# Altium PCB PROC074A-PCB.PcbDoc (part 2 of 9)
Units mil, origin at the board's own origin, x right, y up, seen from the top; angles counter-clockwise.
Board outline 2755.91 x 5300 mil, 10 copper layers (Top Layer, L2-GND, L3-SIG1, L4-GND, L5-PWR/SIG, L6-SIG2, L7-PWR2, L8-SIG3, L9-GND, Bottom Layer), stack 67.57 mil thick; 585 components, 490 nets, 2137 pads, 1150 vias.
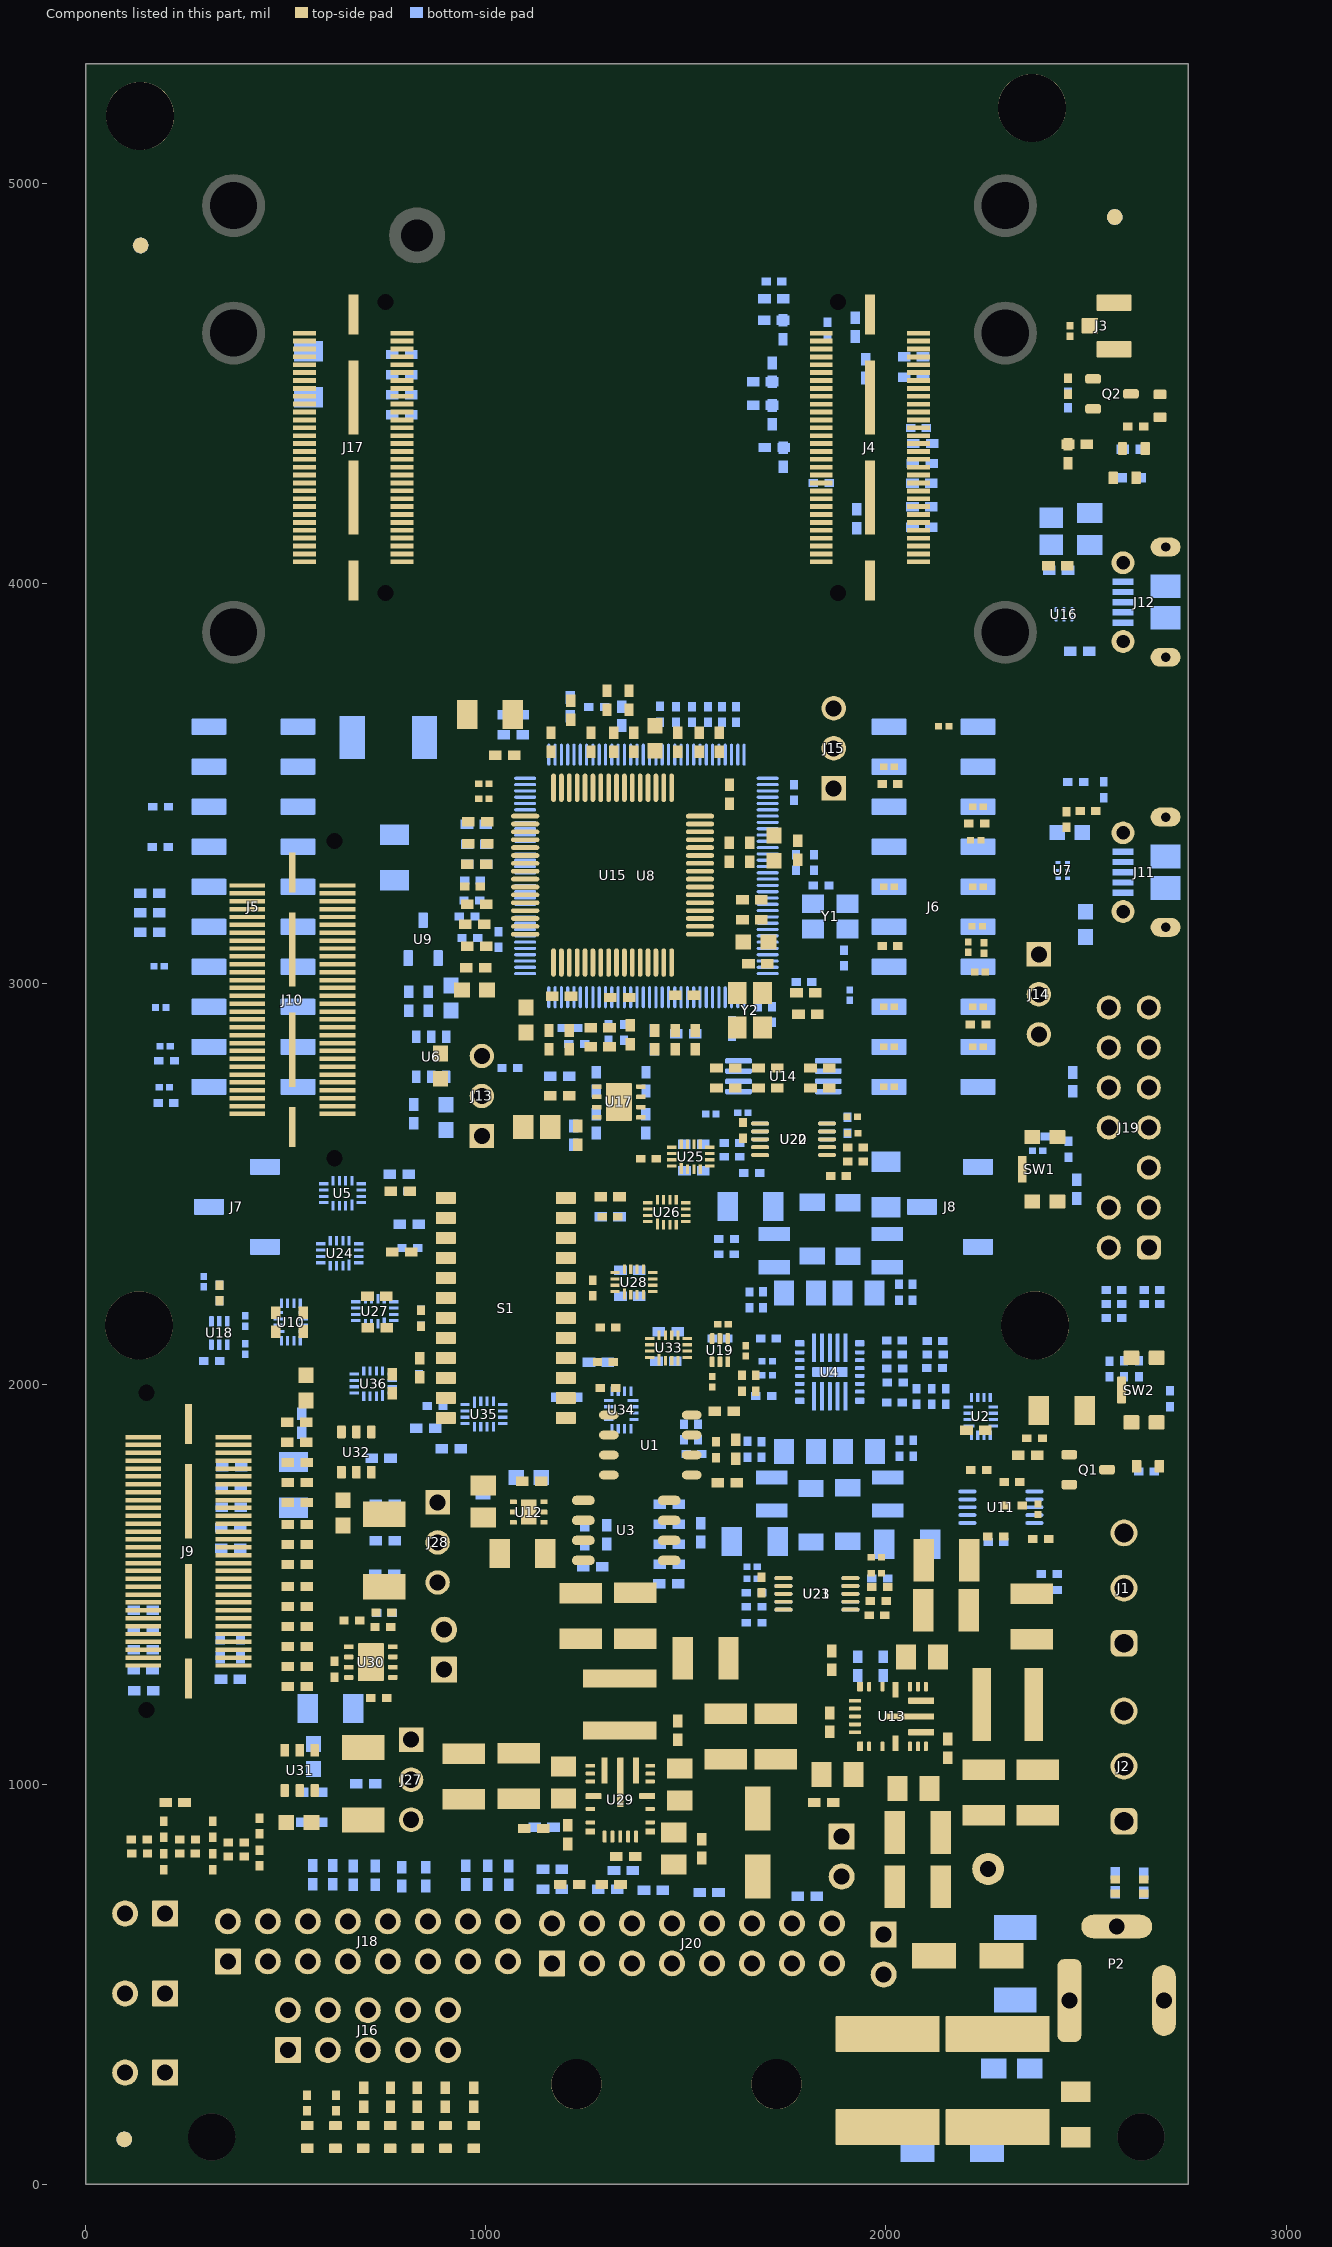
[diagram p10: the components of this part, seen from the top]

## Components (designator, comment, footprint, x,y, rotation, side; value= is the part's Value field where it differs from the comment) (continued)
R313 "CRCW0402280RFKED" 0402 2572.7,753.21 r90 bottom value=280
R314 "CRCW040210K0FKED" 0402L 1670.44,1443.27 r180 bottom value=10.0k
R315 "CRCW040210K0JNED" 0402 1119.37,889.06 r180 top value=10k
R316 "CRCW040210K0FKED" 0402L 1615.37,2568.06 r180 bottom value=10.0k
R317 "CRCW040210K0FKED" 0402L 1980.62,1457.53 r0 top value=10.0k
R318 "CRCW040210K0JNED" 0402 1204.37,874.06 r90 top value=10k
R319 "CRCW02010000Z0ED" 0201 1665.44,1543.27 r180 bottom value=0
R320 "CRCW02010000Z0ED" 0201 1642.37,2678.06 r180 bottom value=0
R321 "CRCW02010000Z0ED" 0201 1976.1,1566.69 r0 top value=0
R322 "CRCW02010000Z0ED" 0201 1665.44,1513.27 r180 bottom value=0
R323 "CRCW02010000Z0ED" 0201 1562.37,2675.06 r180 bottom value=0
R324 "CRCW02010000Z0ED" 0201 1976.1,1526.69 r0 top value=0
R325 "CRCW040210K0FKED" 0402L 1670.44,1478.27 r0 bottom value=10.0k
R326 "CRCW0402510RJNED" 0402 564.7,904.23 r180 bottom value=510
R327 "CRCW040210K0FKED" 0402L 1670.44,1403.27 r0 bottom value=10.0k
R328 "CRCW040210K0FKED" 0402L 1615.37,2602.06 r0 bottom value=10.0k
R329 "ERJ-2GEJ101X" 0402 690.62,1096.53 r180 bottom value=100
R330 "CRCW040210K0FKED" 0402L 1664.37,2527.06 r180 bottom value=10.0k
R331 "CRCW040210K0FKED" 0402L 1984.37,1493.06 r180 top value=10.0k
R332 "CRCW040210K0FKED" 0402L 1977.55,1422.07 r180 top value=10.0k
R338 "CRCW04024K70JNED" 0402 1310.37,2468.06 r0 top value=4.7k
R339 "CRCW04024K70JNED" 0402 727.75,2219.06 r0 top value=4.7k
R346 "ERJ-2GE0R00X" 0402 2090.01,4193.05 r0 bottom value=0
R347 "ERJ-2GE0R00X" 0402 1691.63,4505 r180 bottom value=0
R348 "ERJ-2GE0R00X" 0402 2090.01,4251.03 r0 bottom value=0
R349 "ERJ-2GE0R00X" 0402 1715.25,4528.62 r90 bottom value=0
R350 "ERJ-2GE0R00X" 0402 2455.01,4325.24 r270 top value=0
R351 "ERJ-2GE0R00X" 0402 2478.63,4348.87 r0 top value=0
R353 "ERJ-2GE0R00X" 0402 790,4573.35 r0 bottom value=0
R354 "ERJ-2GE0R00X" 0402 790,4523.35 r0 bottom value=0
R356 "ERJ-2GE0R00X" 0402 790,4473.35 r0 bottom value=0
R357 "ERJ-2GE0R00X" 0402 1719.01,4658.99 r180 bottom value=0
R358 "ERJ-2GE0R00X" 0402 1742.63,4635.37 r270 bottom value=0
R359 "ERJ-2GE0R00X" 0402 1691.63,4445.99 r180 bottom value=0
R360 "ERJ-2GE0R00X" 0402 1715.25,4422.37 r270 bottom value=0
R361 "ERJ-2GE0R00X" 0402 1743.25,4316.38 r270 bottom value=0
R362 "ERJ-2GE0R00X" 0402 1720.63,4341 r180 bottom value=0
R363 "CRCW0402510RJNED" 0402 539.37,1902.06 r270 bottom value=510
R364 "CRCW040210K0FKED" 0402 699.38,1001 r0 bottom value=10.0k
R367 "ERJ-2GEJ101X" 0402 694.38,911 r0 bottom value=100
R368 "ERJ-2GEJ101X" 0402 748.37,1699.06 r180 bottom value=100
R369 "CRCW040210K0FKED" 0402 748.75,1608.06 r0 bottom value=10.0k
R370 "ERJ-2GEJ101X" 0402 747.37,1525.06 r0 bottom value=100
R393 "CRCW02010000Z0ED" 0201_Silk 2245,3090 r270 top value=0
R394 "CRCW02010000Z0ED" 0201_Silk 2206,3092.01 r90 top value=0
R395 "CRCW040210K0FKED" 0402L 621.37,1287.06 r270 top value=10.0k
R396 "CRCW040214K0FKED" 0402L 745.05,1429.01 r0 top value=14.0k
R397 "PNM0402E3502BST1" 0402L 665.05,1409.01 r0 top value=35.0k
R398 "ERJ-2GE0R00X" 0402 790,4423.35 r0 bottom value=0
R399 "CRCW040210K0FKED" 0402L 2021.27,1953.8 r180 bottom value=10.0k
R400 "CRCW040210K0FKED" 0402L 1706.27,2113.8 r0 bottom value=10.0k
R401 "CRCW040210K0FKED" 0402L 2021.27,2108.8 r180 bottom value=10.0k
R402 "CRCW040210K0FKED" 0402L 1694.37,1970.06 r0 bottom value=10.0k
R403 "CRCW040210K0JNED" 0402 1993.37,1295.06 r90 bottom value=10k
R404 "CRCW040210K0JNED" 0402 1929.37,1295.06 r270 bottom value=10k
S1 "218-12LPST" SW_218-12LPST 1050,2190 r180 top
SW1 "KMR243GLFG" SW_KMR243GLFG 2397,2537 r90 top
SW2 "KMR243GLFG" SW_KMR243GLFG 2645,1985 r90 top
TP1 "5001" Keystone5001 2255.37,788.06 r90 top
U1 "TCAN1042HGVDQ1" D0008A_L 1410.94,1847.63 r180 top
U2 "TS3A5018RSVR" RSV0016A 2237.16,1919.11 r0 bottom
U3 "SN65HVDA540QDR" D0008A_N 1350.88,1634.28 r0 top
U4 "LP87524JRNFRQ1" RNF0026C 1859.65,2030.1 r0 bottom locked
U5 "TS3A5018RSVR" RSV0016A 641.63,2477 r90 bottom
U6 "TPS22917DBVR" DBV0006A_L 863.38,2818.06 r90 bottom
U7 "TPD4E004DRYR" DRY0006A#1 2442,3284 r0 bottom
U8 "TM4C1294NCPDTT3" PDT0128A 1401.34,3269.99 r0 bottom
U9 "LM4040C25QDBZR" DBZ0003A_N 843.02,3112 r90 bottom
U10 "TS3A5018RSVR" RSV0016A 512.37,2155.06 r0 bottom
U11 "INA226AIDGST" DGS0010A_L 2287.37,1692.06 r180 bottom
U12 "TPS61240DRVR" DRV0006A 1106.98,1680.06 r180 top
U13 "LM536353QRNLRQ1" RNL0022A 2014.09,1169.06 r90 top
U14 "93LC46B-I/ST" TSSOP-8 1743.65,2769.42 r0 bottom
U15 "FT4232HL" LQFP64_N 1316.69,3271.95 r180 top
U16 "TPD4E004DRYR" DRY0006A#2 2445,3924 r90 bottom
U17 "TPS79601DRBR" DRB0008B#1 1332.36,2705 r0 top
U18 "TMP112AIDRLR" DRL0006A 333.74,2127.66 r90 bottom
U19 "TMP112AIDRLR" DRL0006A 1585.08,2084.69 r270 top
U20 "INA226AIDGST" DGS0010A_L 1769.09,2611.69 r180 top
U21 "INA226AIDGST" DGS0010A_L 1827.4,1475.47 r0 bottom
U22 "INA226AIDGST" DGS0010A_L 1769.09,2611.69 r0 bottom
U23 "INA226AIDGST" DGS0010A_L 1827.4,1475.47 r180 top
U24 "TS3A5018RSVR" RSV0016A 634.63,2326.95 r90 bottom
U25 "TS3A5018RSVR" RSV0016A 1512.06,2568.38 r90 top
U26 "TS3A5018RSVR" RSV0016A 1452.24,2429.55 r90 top
U27 "TS3A5018RSVR" RSV0016A 722.37,2182.06 r90 bottom
U28 "TS3A5018RSVR" RSV0016A 1370,2255 r90 top
U29 "LM536255QRNLRQ1" RNL0022A 1335.93,960.36 r180 top
U30 "TPS79601DRBR" DRB0008B#2 712.41,1305 r180 top
U31 "TPS22917DBVR" DBV0006A_L 534.7,1034.23 r270 top
U32 "TPS22917DBVR" DBV0006A_L 676.37,1830.06 r90 top
U33 "TS3A5018RSVR" RSV0016A 1456.59,2090.24 r90 top
U34 "TS3A5018RSVR" RSV0016A 1338.75,1935.3 r180 bottom
U35 "TS3A5018RSVR" RSV0016A 995,1925 r270 bottom
U36 "TS3A5018RSVR" RSV0016A 718.37,2001.06 r90 bottom
Y1 "NX3225SA-16.000M-STD-CRS-2" NDK_NX3225SA 1861,3169 r270 bottom
Y2 "NX3225SA-12.000M-STD-CRS-2" NDK_NX3225SA 1659.85,2934.59 r180 top
ZZ1 "This Assembly Note is for PCB labels only" AssemblyNoteLabel -628,5874 r0 top
ZZ2 "These assemblies are ESD sensitive, ESD precautions shall be observed." AssemblyNote -628,5765.11 r0 top
ZZ3 "These assemblies must be clean and free from flux and all contaminants. Use of no clean flux is not acceptable." AssemblyNote -628,5676.56 r0 top
ZZ4 "These assemblies must comply with workmanship standards IPC-A-610 Class 2, unless otherwise specified." AssemblyNote -628,5588 r0 top

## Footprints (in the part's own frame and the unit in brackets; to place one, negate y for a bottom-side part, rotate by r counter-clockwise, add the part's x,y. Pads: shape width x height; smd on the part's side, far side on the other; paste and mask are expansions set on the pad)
0201 [mm] "Data from Kemet datasheet CC101_COM dated 7/28/11"
  rect 0.46x0.42 smd: 1(-0.33,0) 2(0.33,0)
  body extent -0.31,-0.16 0.31,0.16, height 0.26
0201_Silk [mm] "Data from Kemet datasheet CC101_COM dated 7/28/11"
  rect 0.46x0.42 smd: 1(-0.33,0) 2(0.33,0)
  silkscreen extent -0.75,-0.4 0.75,0.4, body extent -0.31,-0.16 0.31,0.16, height 0.26
0402 [mm] "0402 from SM-752 data"
  rect 0.8x0.6 smd: 1(-0.6,0) 2(0.6,0)
  silkscreen extent -1.22,-0.52 1.22,0.52, body extent -0.55,-0.3 0.55,0.3, height 0.6
0402_065 [mm] "0402"
  rect 0.8x0.6 smd: 1(-0.6,0) 2(0.6,0)
  silkscreen extent -1.22,-0.52 1.22,0.52, body extent -0.55,-0.3 0.55,0.3, height 0.65
0402_065L [mm] "0402"
  rect 0.6x0.5 smd: 1(-0.5,0) 2(0.5,0)
  body extent -0.55,-0.3 0.55,0.3, height 0.65
0402L [mm] "0402 from SM-752 data"
  rect 0.6x0.5 smd: 1(-0.5,0) 2(0.5,0)
  body extent -0.55,-0.3 0.55,0.3, height 0.6
597D_Z [mm] "SMD, 2-Leads, Body 6.2x6mm"
  rrect4% 2.3x6.6 smd: 1(-2.95,0) 2(2.95,0)
  body extent -4.5,-3.2 3.1,3.2, height 6.4
0603 [mm] "0603 from SM-752 data"
  rect 1x0.95 smd: 1(-0.8,0) 2(0.8,0)
  silkscreen extent -1.52,-0.69 1.52,0.69, body extent -0.87,-0.47 0.87,0.47, height 1
0805 [mm] "0805 from SM-752 data"
  rect 1.3x1.5 smd: 1(-0.85,0) 2(0.85,0)
  silkscreen extent -1.72,-0.97 1.72,0.97, body extent -1.1,-0.72 1.1,0.72, height 1.45
0805_HV [mil] "0805 with 30mil clearance between pads"
  rect 50x63 smd: 1(-40,0) 2(40,0)
  silkscreen extent -74,-40 74,40, body extent -43,-29 43,29, height 57
1206 [mm] "1206 from SM-752 data"
  rect 1.3x1.85 smd: 1(-1.45,0) 2(1.45,0)
  silkscreen extent -2.4,-1.21 2.4,1.21, body extent -1.7,-0.9 1.7,0.9, height 1.35
1206_180 [mm] "1206_180"
  rect 1.1x1.6 smd: 1(-1.7,0) 2(1.7,0)
  silkscreen extent -0.9,-1 0.9,1, body extent -1.75,-0.95 1.75,0.95, height 1.8
1210 [mm] "1210 from SM-752 data"
  rect 1.3x2.7 smd: 1(-1.45,0) 2(1.45,0)
  silkscreen extent -2.32,-1.57 2.32,1.57, body extent -1.7,-1.35 1.7,1.35, height 1.35
1210_270 [mm] "1210"
  rect 1.3x2.7 smd: 1(-1.45,0) 2(1.45,0)
  silkscreen extent -2.32,-1.57 2.32,1.57, body extent -1.7,-1.35 1.7,1.35, height 2.7
2010 [mm] "Chip Capacitor, Body 5.08x2.54mm, IPC Medium Density"
  rect 1.6x2.7 smd: 1(-2.3,0) 2(2.3,0)
  silkscreen extent -3.42,-1.65 3.42,1.65, body extent -2.73,-1.45 2.73,1.45, height 1.66
AssemblyNote [mil] "Assembly Note"
AssemblyNoteLabel [mil] "Assembly Note for PCB Labels"
CE_Mark_5mm [mil] "Minimum text height for CE Mark"
  silkscreen extent -138,-98 138,98
CONN_105017-0001 [mm] "Molex Micro USB-B"
  rect 0.4x1.35 smd: 1(-1.3,1.35) 2(-0.65,1.35) 3(0,1.35) 4(0.65,1.35) 5(1.3,1.35)
  oval 1.2x1.9 hole 0.6 slot 1.3 at 90 deg: 6(-3.5,-1.35) 9(3.5,-1.35)
  rect 1.5x1.9 smd: 7(-1,-1.35) 8(1,-1.35)
  round 1.45 hole 0.85: 10(2.5,1.35) 11(-2.5,1.35)
  Top Layer region: 3.5,-2.3 2.3,-2.3 2.3,-0.4 3.5,-0.4
  Top Layer region: -3.5,-0.4 -2.3,-0.4 -2.3,-2.3 -3.5,-2.3
  silkscreen extent -4.1,-0.2 4.1,1.4, body extent -4.1,-3.93 4.1,1.5, height 2.72
CUI_PJ-002AH [mm] "DC POWER JACK, R/A, TH"
  rrect50% 1.5x5.25 hole 1 square: 1(-3,0)
  oval 1.5x4.5 hole 1 square: 2(3,0)
  oval 4.5x1.5 hole 1 square: 3(0,4.7)
  silkscreen extent -4.1,-4.5 10.7,4.5, body extent -3.7,-4.5 10.7,4.9, height 11
D0008A_L [mm] "SOIC, 8-Leads, Body 4.9x3.9mm, Pitch 1.27mm, IPC High Density"
  oval 1.25x0.55 smd: 1(-2.625,1.905) 2(-2.625,0.635) 3(-2.625,-0.635) 4(-2.625,-1.905) 5(2.625,-1.905) 6(2.625,-0.635) 7(2.625,0.635) 8(2.625,1.905)
  silkscreen extent -3.1,-2.5 0.9,2.5, body extent -3,-2.45 3,2.45, height 1.63
D0008A_N [mm] "SOIC, 8-Leads, Body 4.9x3.9mm, Pitch 1.27mm, IPC Medium Density"
  oval 1.45x0.6 smd: 1(-2.725,1.905) 2(-2.725,0.635) 3(-2.725,-0.635) 4(-2.725,-1.905) 5(2.725,-1.905) 6(2.725,-0.635) 7(2.725,0.635) 8(2.725,1.905)
  silkscreen extent -3.3,-2.5 0.9,2.5, body extent -3,-2.45 3,2.45, height 1.63
DBV0006A_L [mm] "SOT23, 6-Leads, Body 2.9x1.6mm, Pitch 0.95mm, Lead Span 2.8mm, IPC High Density"
  rrect18% 0.8x0.55 smd: 1(-1.275,0.95) 2(-1.275,0) 3(-1.275,-0.95) 4(1.275,-0.95) 5(1.275,0) 6(1.275,0.95)
  silkscreen extent -1.55,-1.53 0.55,1.53, body extent -1.42,-1.46 1.42,1.46, height 1.12
DBZ0003A_N [mm] "SOT23, 3-Leads, Body 2.9x1.3mm, Pitch 0.95mm, Lead Span 2.4mm, IPC Medium Density"
  rrect17% 1x0.6 smd: 1(-1.2,0.95) 2(-1.2,-0.95) 3(1.2,0)
  silkscreen extent 0.2,-1.5 0.7,1.5, body extent -1.26,-1.46 1.26,1.46, height 0.98
DFE252012P [mm] "TOKO, Pad sizes increased as per request"
  rect 0.9x2 smd: 1(-1.05,0) 2(1.05,0)
  silkscreen extent -0.3,-1.2 0.3,1.2, body extent -1.35,-1.1 1.35,1.1, height 1.2
DGS0010A_L [mm] "TSSOP, 10-Leads, Body 3x3mm, Pitch 0.5mm, IPC High Density"
  oval 1.15x0.25 smd: 1(-2.125,1) 2(-2.125,0.5) 3(-2.125,0) 4(-2.125,-0.5) 5(-2.125,-1) 6(2.125,-1) 7(2.125,-0.5) 8(2.125,0) 9(2.125,0.5) 10(2.125,1)
  silkscreen extent -2.65,-1.55 0.9,1.55, body extent -2.45,-1.5 2.45,1.5, height 0.96
DRB0008B#1 [mm] "SON, 8-Leads, Body 3x3mm, Pitch 0.65mm, Thermal Pad 2.4x1.65mm, TI Recommended"
  rrect33% 0.6x0.3 smd: 1(-1.4,0.975) 2(-1.4,0.325) 3(-1.4,-0.325) 4(-1.4,-0.975) 5(1.4,-0.975) 6(1.4,-0.325) 7(1.4,0.325) 8(1.4,0.975)
  rrect9% 1.47x1.06 on Top Paste: 9(0,-0.63) 9(0,0.63)
  rrect6% 1.65x2.4 smd paste-1.2: 9(0,0)
  silkscreen extent -1.73,-1.73 1.73,1.73, body extent -1.5,-1.5 1.5,1.5, height 0.96
DRB0008B#2 [mm] "SON, 8-Leads, Body 3x3mm, Pitch 0.65mm, Thermal Pad 2.4x1.65mm, TI Recommended"
  rrect33% 0.6x0.3 smd: 1(-1.4,0.975) 2(-1.4,0.325) 3(-1.4,-0.325) 4(-1.4,-0.975) 5(1.4,-0.975) 6(1.4,-0.325) 7(1.4,0.325) 8(1.4,0.975)
  rrect6% 1.65x2.4 smd paste-1.2: 9(0,0)
  silkscreen extent -1.73,-1.73 1.73,1.73, body extent -1.5,-1.5 1.5,1.5, height 0.96
DRL0006A [mm] "SOTFL, 6-Flat Leads, Body 1.2x1.6x0.6mm, Pitch 0.5mm, TI recommended"
  rrect33% 0.67x0.3 smd: 1(-0.74,0.5) 2(-0.74,0) 3(-0.74,-0.5) 4(0.74,-0.5) 5(0.74,0) 6(0.74,0.5)
  silkscreen extent -0.9,-0.95 0.5,0.95, body extent -0.8,-0.8 0.8,0.8, height 0.61
DRV0006A [mm] "SON, 6-Leads, Body 2x2mm, Pitch 0.65mm, Thermal Pad 1.6x1mm, TI Recommended"
  rrect33% 0.45x0.3 smd: 1(-0.975,0.65) 2(-0.975,0) 3(-0.975,-0.65) 4(0.975,-0.65) 5(0.975,0) 6(0.975,0.65)
  rrect14% 1x0.7 on Top Paste: 7(0,0.45) 7(0,-0.45)
  rrect10% 1x1.6 smd paste-0.5: 7(0,0)
  silkscreen extent -1.05,-1.2 1.05,1.2, body extent -1.05,-1.05 1.05,1.05, height 0.81
DRY0006A#1 [mm] "PSON, 6-Leads, Body 1x1.45mm, Pitch 0.5mm, TI Recommended"
  rect 0.35x0.2 smd: 1(-0.275,0.5)
  rect 0.3x0.2 smd: 2(-0.3,0) 3(-0.3,-0.5) 4(0.3,-0.5) 5(0.3,0) 6(0.3,0.5)
  silkscreen extent -0.5,-0.85 0.2,0.85, body extent -0.53,-0.75 0.53,0.75, height 0.61
DRY0006A#2 [mm] "PSON, 6-Leads, Body 1x1.45mm, Pitch 0.5mm, TI Recommended"
  rrect50% 0.35x0.2 smd: 1(-0.275,0.5)
  rrect50% 0.3x0.2 smd: 2(-0.3,0) 3(-0.3,-0.5) 4(0.3,-0.5) 5(0.3,0) 6(0.3,0.5)
  body extent -0.5,-0.72 0.5,0.73, height 0.58
FCC_disclaimer [mil]
Fiducial10-20 [mm]
  round 1 smd mask+0.5: 1(0,0)
  Top Layer keep-out circle w1.178: c0,0 r0.5
IEC_HotSurface_Small [mil]
  silkscreen extent -107,-93 107,92
Johnson_128-0711-201 [mm] "UMC Straight Jack Receptacle, 50 Ohm, SMT"
  rrect10% 1x1.05 smd: 1(0,1.525)
  rrect10% 1.05x2.2 smd: 2(-1.475,0) 3(1.475,0)
  silkscreen extent -0.6,-1.3 0.6,-1.3, body extent -1.5,-1.55 1.5,1.55, height 1.25
Keystone5001 [mil] "For Keystone 500x miniature loop terminals"
  round 80 hole 40: 1(0,0)
  silkscreen extent -52,-52 52,52, body extent -49,-49 49,49, height 182
Label_650x200 [mil] "Thermal Transfer Label"
  round 1 on Mech13: 0(0,0)
  silkscreen extent -325,-100 325,100, body extent -325,-100 325,100, height 1
LQFP64_N [mm] "Thin QFP, 64-Leads, Body 10x10mm, Pitch 0.5mm, IPC Medium Density"
  oval 1.8x0.3 smd: 1(-5.55,3.75) 2(-5.55,3.25) 3(-5.55,2.75) 4(-5.55,2.25) 5(-5.55,1.75) 6(-5.55,1.25) 7(-5.55,0.75) 8(-5.55,0.25) 9(-5.55,-0.25) 10(-5.55,-0.75) 11(-5.55,-1.25) 12(-5.55,-1.75) 13(-5.55,-2.25) 14(-5.55,-2.75) 15(-5.55,-3.25) 16(-5.55,-3.75) 33(5.55,-3.75) 34(5.55,-3.25) 35(5.55,-2.75) 36(5.55,-2.25) 37(5.55,-1.75) 38(5.55,-1.25) 39(5.55,-0.75) 40(5.55,-0.25) 41(5.55,0.25) 42(5.55,0.75) 43(5.55,1.25) 44(5.55,1.75) 45(5.55,2.25) 46(5.55,2.75) 47(5.55,3.25) 48(5.55,3.75)
  oval 0.3x1.8 smd: 17(-3.75,-5.55) 18(-3.25,-5.55) 19(-2.75,-5.55) 20(-2.25,-5.55) 21(-1.75,-5.55) 22(-1.25,-5.55) 23(-0.75,-5.55) 24(-0.25,-5.55) 25(0.25,-5.55) 26(0.75,-5.55) 27(1.25,-5.55) 28(1.75,-5.55) 29(2.25,-5.55) 30(2.75,-5.55) 31(3.25,-5.55) 32(3.75,-5.55) 49(3.75,5.55) 50(3.25,5.55) 51(2.75,5.55) 52(2.25,5.55) 53(1.75,5.55) 54(1.25,5.55) 55(0.75,5.55) 56(0.25,5.55) 57(-0.25,5.55) 58(-0.75,5.55) 59(-1.25,5.55) 60(-1.75,5.55) 61(-2.25,5.55) 62(-2.75,5.55) 63(-3.25,5.55) 64(-3.75,5.55)
  silkscreen extent -5.68,-4.25 4.25,4.57, body extent -5,-5 5,5, height 1.6
Molex_0022284033 [mm] "Header, 2.54mm, 3x1, TH"
  rect 1.55x1.55 hole 1.02: 1(-2.54,0)
  round 1.55 hole 1.02: 2(0,0) 3(2.54,0)
  silkscreen extent -3.81,-1.24 3.81,1.5, body extent -3.81,-1.24 3.81,1.24, height 8.4
MTGNP431H431 [mil] "MOUNTING HOLE, NON PLATED, 4.318MM DRILL"
  round 170 hole 170 unplated: ""(0,0)
  Keep-Out Layer circle w0.98: c0,0 r125
  silkscreen extent -97,-97 97,97
NDK_NX3225SA [mm] "NDK"
  rect 1.2x1.4 smd: 1(-0.8,1.1) 2(-0.8,-1.1) 3(0.8,-1.1) 4(0.8,1.1)
  body extent -1.3,-1.65 1.3,1.65, height 0.7
On-Shore_OSTTE030161 [mm] "Terminal Block, 3.5mm, 3x1, TH"
  rrect50% 1.7x1.7 hole 1.2: 1(-3.5,0)
  round 1.7 hole 1.2: 2(0,0) 3(3.5,0)
  silkscreen extent -5.25,-3.6 5.25,4.05, body extent -5.75,-3.6 5.75,3.4, height 8.4
PDT0128A [mm] "Thin QFP, 128-Leads, Body 14x14mm, Pitch 0.4mm"
  oval 1.4x0.2 smd: 1(-7.7,6.2) 2(-7.7,5.8) 3(-7.7,5.4) 4(-7.7,5) 5(-7.7,4.6) 6(-7.7,4.2) 7(-7.7,3.8) 8(-7.7,3.4) 9(-7.7,3) 10(-7.7,2.6) 11(-7.7,2.2) 12(-7.7,1.8) 13(-7.7,1.4) 14(-7.7,1) 15(-7.7,0.6) 16(-7.7,0.2) 17(-7.7,-0.2) 18(-7.7,-0.6) 19(-7.7,-1) 20(-7.7,-1.4) 21(-7.7,-1.8) 22(-7.7,-2.2) 23(-7.7,-2.6) 24(-7.7,-3) 25(-7.7,-3.4) 26(-7.7,-3.8) 27(-7.7,-4.2) 28(-7.7,-4.6) 29(-7.7,-5) 30(-7.7,-5.4) 31(-7.7,-5.8) 32(-7.7,-6.2) 65(7.7,-6.2) 66(7.7,-5.8) 67(7.7,-5.4) 68(7.7,-5) 69(7.7,-4.6) 70(7.7,-4.2) 71(7.7,-3.8) 72(7.7,-3.4) 73(7.7,-3) 74(7.7,-2.6) 75(7.7,-2.2) 76(7.7,-1.8) 77(7.7,-1.4) 78(7.7,-1) 79(7.7,-0.6) 80(7.7,-0.2) 81(7.7,0.2) 82(7.7,0.6) 83(7.7,1) 84(7.7,1.4) 85(7.7,1.8) 86(7.7,2.2) 87(7.7,2.6) 88(7.7,3) 89(7.7,3.4) 90(7.7,3.8) 91(7.7,4.2) 92(7.7,4.6) 93(7.7,5) 94(7.7,5.4) 95(7.7,5.8) 96(7.7,6.2)
  oval 0.2x1.4 smd: 33(-6.2,-7.7) 34(-5.8,-7.7) 35(-5.4,-7.7) 36(-5,-7.7) 37(-4.6,-7.7) 38(-4.2,-7.7) 39(-3.8,-7.7) 40(-3.4,-7.7) 41(-3,-7.7) 42(-2.6,-7.7) 43(-2.2,-7.7) 44(-1.8,-7.7) 45(-1.4,-7.7) 46(-1,-7.7) 47(-0.6,-7.7) 48(-0.2,-7.7) 49(0.2,-7.7) 50(0.6,-7.7) 51(1,-7.7) 52(1.4,-7.7) 53(1.8,-7.7) 54(2.2,-7.7) 55(2.6,-7.7) 56(3,-7.7) 57(3.4,-7.7) 58(3.8,-7.7) 59(4.2,-7.7) 60(4.6,-7.7) 61(5,-7.7) 62(5.4,-7.7) 63(5.8,-7.7) 64(6.2,-7.7) 97(6.2,7.7) 98(5.8,7.7) 99(5.4,7.7) 100(5,7.7) 101(4.6,7.7) 102(4.2,7.7) 103(3.8,7.7) 104(3.4,7.7) 105(3,7.7) 106(2.6,7.7) 107(2.2,7.7) 108(1.8,7.7) 109(1.4,7.7) 110(1,7.7) 111(0.6,7.7) 112(0.2,7.7) 113(-0.2,7.7) 114(-0.6,7.7) 115(-1,7.7) 116(-1.4,7.7) 117(-1.8,7.7) 118(-2.2,7.7) 119(-2.6,7.7) 120(-3,7.7) 121(-3.4,7.7) 122(-3.8,7.7) 123(-4.2,7.7) 124(-4.6,7.7) 125(-5,7.7) 126(-5.4,7.7) 127(-5.8,7.7) 128(-6.2,7.7)
  silkscreen extent -7.2,-6.3 6.3,6.99, body extent -8,-8 8,8, height 1.07
RNF0026C [mm] "QFN, 26-Leads, Body 4x4.5mm, Pitch 0.5mm"
  rrect25% 0.6x0.4 smd paste-0.3: 1(-1.9,1.825) 8(-1.9,-1.825) 14(1.9,-1.825) 21(1.9,1.825)
  rrect40% 0.6x0.25 smd paste+0: 2(-1.9,1.25) 3(-1.9,0.75) 4(-1.9,0.25) 5(-1.9,-0.25) 6(-1.9,-0.75) 7(-1.9,-1.25) 15(1.9,-1.25) 16(1.9,-0.75) 17(1.9,-0.25) 18(1.9,0.25) 19(1.9,0.75) 20(1.9,1.25)
  rrect40% 0.25x1.82 smd paste-1: 9(-1,-1.54) 10(-0.5,-1.54) 11(0,-1.54) 12(0.5,-1.54) 13(1,-1.54) 22(1,1.54) 23(0.5,1.54) 24(0,1.54) 25(-0.5,1.54) 26(-1,1.54)
  rrect15% 2.24x0.66 smd paste-1: 27(0,0)
  rrect33% 0.6x0.3 on Bottom Paste: ""(-1.9,-1.775) ""(-1.9,1.775) ""(1.9,-1.775) ""(1.9,1.775)
  rrect33% 0.3x0.825 on Bottom Paste: ""(-1.575,-2.037) ""(-1.575,2.037) ""(1.575,-2.037) ""(1.575,2.037)
  rrect40% 0.25x0.81 on Bottom Paste: ""(-1,-2.045) ""(-1,-1.035) ""(-1,1.035) ""(-1,2.045) ""(-0.5,-2.045) ""(-0.5,-1.035) ""(-0.5,1.035) ""(-0.5,2.045) ""(0,-2.045) ""(0,-1.035) ""(0,1.035) ""(0,2.045) ""(0.5,-2.045) ""(0.5,-1.035) ""(0.5,1.035) ""(0.5,2.045) ""(1,-2.045) ""(1,-1.035) ""(1,1.035) ""(1,2.045)
  rrect15% 0.98x0.66 on Bottom Paste: ""(-0.59,0) ""(0.59,0)
  Top Layer region: -1.775,-2.4 -1.775,-1.675 -1.771,-1.656 -1.76,-1.64 -1.744,-1.629 -1.725,-1.625 -1.725,-1.625 -1.475,-1.625 -1.456,-1.629 -1.44,-1.64 -1.429,-1.656 -1.425,-1.675 -1.425,-1.675 -1.425,-2.4 -1.429,-2.419 -1.44,-2.435 -1.456,-2.446 -1.475,-2.45 -1.475,-2.45 -1.725,-2.45 -1.744,-2.446 -1.76,-2.435 -1.771,-2.419 -1.775,-2.4
  Top Layer region: 1.425,-2.4 1.425,-1.675 1.429,-1.656 1.44,-1.64 1.456,-1.629 1.475,-1.625 1.475,-1.625 1.725,-1.625 1.744,-1.629 1.76,-1.64 1.771,-1.656 1.775,-1.675 1.775,-1.675 1.775,-2.4 1.771,-2.419 1.76,-2.435 1.744,-2.446 1.725,-2.45 1.725,-2.45 1.475,-2.45 1.456,-2.446 1.44,-2.435 1.429,-2.419 1.425,-2.4
  Top Layer region: 1.425,1.675 1.425,2.4 1.429,2.419 1.44,2.435 1.456,2.446 1.475,2.45 1.475,2.45 1.725,2.45 1.744,2.446 1.76,2.435 1.771,2.419 1.775,2.4 1.775,2.4 1.775,1.675 1.771,1.656 1.76,1.64 1.744,1.629 1.725,1.625 1.725,1.625 1.475,1.625 1.456,1.629 1.44,1.64 1.429,1.656 1.425,1.675
  Top Layer region: -1.775,1.675 -1.775,2.4 -1.771,2.419 -1.76,2.435 -1.744,2.446 -1.725,2.45 -1.725,2.45 -1.475,2.45 -1.456,2.446 -1.44,2.435 -1.429,2.419 -1.425,2.4 -1.425,2.4 -1.425,1.675 -1.429,1.656 -1.44,1.64 -1.456,1.629 -1.475,1.625 -1.475,1.625 -1.725,1.625 -1.744,1.629 -1.76,1.64 -1.771,1.656 -1.775,1.675
  silkscreen extent -2.45,-2.7 2.45,2.7, body extent -2,-2.25 2,2.25, height 0.9
RNL0022A [mm] "VQFN-HR-22"
  rrect25% 0.6x0.4 smd: 1(-1.9,2) 17(1.9,2)
  rrect40% 0.6x0.25 smd: 2(-1.9,1.425) 3(-1.9,0.575) 5(-1.9,-1.175) 6(-1.9,-1.675) 7(-1.9,-2.175) 11(1.9,-2.175) 12(1.9,-1.675) 13(1.9,-1.175) 15(1.9,0.575) 16(1.9,1.425)
  rrect25% 1x0.4 smd paste-0.25: 4(-1.7,-0.25) 14(1.7,-0.25)
  rrect25% 0.4x0.4 on Top Paste: 4A(-2,-0.25) 4B(-1.4,-0.25) 14A(1.4,-0.25) 14B(2,-0.25)
  rrect25% 0.4x1.65 smd paste-0.25: 8(-1,-1.875) 10(1,-1.875)
  rrect25% 0.4x0.66 on Top Paste: 8A(-1,-1.445) 8B(-1,-2.305) 10A(1,-1.445) 10B(1,-2.305)
  rrect25% 0.4x3.15 smd paste-0.25: 9(0,-1.125)
  rrect25% 0.4x0.63 on Top Paste: 9A(0,0.12) 9B(0,-0.71) 9C(0,-1.54) 9D(0,-2.37)
  rrect40% 0.25x0.75 smd: 18(1,2.325) 19(0.5,2.325) 20(0,2.325) 21(-0.5,2.325) 22(-1,2.325)
  body extent -2,-2.5 2,2.5, height 0.9
RSV0016A [mm] "QFN, 16-Leads, Body 1.8x2.6mm, Pitch 0.4mm, TI Recommended"
  rect 0.7x0.2 smd: 1(-0.75,0.6)
  rect 0.6x0.2 smd: 2(-0.8,0.2) 3(-0.8,-0.2) 4(-0.8,-0.6) 9(0.8,-0.6) 10(0.8,-0.2) 11(0.8,0.2) 12(0.8,0.6)
  rect 0.2x0.6 smd: 5(-0.6,-1.2) 6(-0.2,-1.2) 7(0.2,-1.2) 8(0.6,-1.2) 13(0.6,1.2) 14(0.2,1.2) 15(-0.2,1.2) 16(-0.6,1.2)
  silkscreen extent -1.08,-1.33 1.08,1.45, body extent -0.92,-1.32 0.92,1.33, height 0.56
Samtec_QSH-030-01-X-D-A [mm] "Receptacle, 0.5 mm, 30x2, TH"
  rect 2.27x0.279 smd: 1(-2.865,7.25) 2(2.865,7.25) 3(-2.865,6.75) 4(2.865,6.75) 5(-2.865,6.25) 6(2.865,6.25) 7(-2.865,5.75) 8(2.865,5.75) 9(-2.865,5.25) 10(2.865,5.25) 11(-2.865,4.75) 12(2.865,4.75) 13(-2.865,4.25) 14(2.865,4.25) 15(-2.865,3.75) 16(2.865,3.75) 17(-2.865,3.25) 18(2.865,3.25) 19(-2.865,2.75) 20(2.865,2.75) 21(-2.865,2.25) 22(2.865,2.25) 23(-2.865,1.75) 24(2.865,1.75) 25(-2.865,1.25) 26(2.865,1.25) 27(-2.865,0.75) 28(2.865,0.75) 29(-2.865,0.25) 30(2.865,0.25) 31(-2.865,-0.25) 32(2.865,-0.25) 33(-2.865,-0.75) 34(2.865,-0.75) 35(-2.865,-1.25) 36(2.865,-1.25) 37(-2.865,-1.75) 38(2.865,-1.75) 39(-2.865,-2.25) 40(2.865,-2.25) 41(-2.865,-2.75) 42(2.865,-2.75) 43(-2.865,-3.25) 44(2.865,-3.25) 45(-2.865,-3.75) 46(2.865,-3.75) 47(-2.865,-4.25) 48(2.865,-4.25) 49(-2.865,-4.75) 50(2.865,-4.75) 51(-2.865,-5.25) 52(2.865,-5.25) 53(-2.865,-5.75) 54(2.865,-5.75) 55(-2.865,-6.25) 56(2.865,-6.25) 57(-2.865,-6.75) 58(2.865,-6.75) 59(-2.865,-7.25) 60(2.865,-7.25)
  round 0 hole 1.02 unplated mask+0.635: MH1(2.67,10.065) MH2(2.67,-10.065)
  rect 0.43x2.54 smd: MP1(0,8.065) MP4(0,-8.065)
  rect 0.43x4.7 smd: MP2(0,3.175) MP3(0,-3.175)
  silkscreen extent -3.9,-10.66 3.62,10.66, body extent -3.75,-10.64 3.75,10.67, height 3.25
Samtec_QTH-030-01-x-D-A [mil] "Header (Shrouded), 19.7mil, 30x2, SMT"
  rect 12x57 smd: 1(-285.7,121.5) 2(-285.7,-121.5) 3(-266,121.5) 4(-266,-121.5) 5(-246.3,121.5) 6(-246.3,-121.5) 7(-226.6,121.5) 8(-226.6,-121.5) 9(-206.9,121.5) 10(-206.9,-121.5) 11(-187.2,121.5) 12(-187.2,-121.5) 13(-167.5,121.5) 14(-167.5,-121.5) 15(-147.8,121.5) 16(-147.8,-121.5) 17(-128.1,121.5) 18(-128.1,-121.5) 19(-108.4,121.5) 20(-108.4,-121.5) 21(-88.7,121.5) 22(-88.7,-121.5) 23(-69,121.5) 24(-69,-121.5) 25(-49.3,121.5) 26(-49.3,-121.5) 27(-29.6,121.5) 28(-29.6,-121.5) 29(-9.9,121.5) 30(-9.9,-121.5) 31(9.8,121.5) 32(9.8,-121.5) 33(29.5,121.5) 34(29.5,-121.5) 35(49.2,121.5) 36(49.2,-121.5) 37(68.9,121.5) 38(68.9,-121.5) 39(88.6,121.5) 40(88.6,-121.5) 41(108.3,121.5) 42(108.3,-121.5) 43(128,121.5) 44(128,-121.5) 45(147.7,121.5) 46(147.7,-121.5) 47(167.4,121.5) 48(167.4,-121.5) 49(187.1,121.5) 50(187.1,-121.5) 51(206.8,121.5) 52(206.8,-121.5) 53(226.5,121.5) 54(226.5,-121.5) 55(246.2,121.5) 56(246.2,-121.5) 57(265.9,121.5) 58(265.9,-121.5) 59(285.6,121.5) 60(285.6,-121.5)
  round 28 hole 40 unplated mask+11.5: MH1(-364,80) MH2(364,80)
  rect 100x25 smd: MP1(-332.7,0) MP4(332.3,0)
  rect 185x25 smd: MP2(-125.2,0) MP3(124.8,0)
  silkscreen extent -394,-118 394,131, body extent -394,-140 394,140, height 170
Samtec_SSM-103-x-SV [mm] "Receptacle, 2.54mm, 3x1, SMT"
  rrect10% 1.02x1.905 smd: 1(-2.54,-1.777) 2(0,1.777) 3(2.54,-1.777)
  silkscreen extent -3.81,-2.28 3.81,1.28, body extent -3.81,-2.29 3.81,2.29, height 7.51
Samtec_SSM-110-x-DV [mm] "Receptacle, 2.54mm, 10x2, SMT"
  rrect10% 1.02x2.22 smd: 1(-11.43,2.825) 2(-11.43,-2.825) 3(-8.89,2.825) 4(-8.89,-2.825) 5(-6.35,2.825) 6(-6.35,-2.825) 7(-3.81,2.825) 8(-3.81,-2.825) 9(-1.27,2.825) 10(-1.27,-2.825) 11(1.27,2.825) 12(1.27,-2.825) 13(3.81,2.825) 14(3.81,-2.825) 15(6.35,2.825) 16(6.35,-2.825) 17(8.89,2.825) 18(8.89,-2.825) 19(11.43,2.825) 20(11.43,-2.825)
  silkscreen extent -13.02,-2.54 12.7,2.54, body extent -12.7,-3.52 12.7,3.52, height 7.42
Samtec_TSW-107-07-L-D-006 [mm] "Header, 2.54mm, 13 Pos, TH"
  rrect50% 1.53x1.53 hole 1.02: 1(-1.27,7.62)
  round 1.53 hole 1.02: 2(1.27,7.62) 3(-1.27,5.08) 4(1.27,5.08) 5(-1.27,2.54) 7(-1.27,0) 8(1.27,0) 9(-1.27,-2.54) 10(1.27,-2.54) 11(-1.27,-5.08) 12(1.27,-5.08) 13(-1.27,-7.62) 14(1.27,-7.62)
  body extent -2.54,-8.89 2.54,8.89, height 8.38
SM_RADIAL_C [mm] "5 x 5.8mm:  Panasonic C"
  rect 2.8x1.6 smd: 1(-2.15,0) 2(2.15,0)
  silkscreen extent -2.75,-2.75 2.75,2.75, body extent -2.75,-2.75 2.75,2.75, height 6.1
SMB [mil] "Molded Diode, 2-Leads, Body 5.4x3.6mm, IPC Medium Density, based on OnSemi component dimensions"
  rect 85x107.99 smd: 1(-87.01,0) 2(87.01,0)
  silkscreen extent -155,-82 125,82, body extent -106,-71 106,71, height 91
SML-P1_GREEN [mm] "ROHM"
  rect 0.5x0.6 smd: 1(-0.45,0) 2(0.45,0)
  silkscreen extent -0.95,-0.3 -0.95,0.3, body extent -0.53,-0.33 0.53,0.33, height 0.25
SOT-23 [mm] "SOT23, 3-Leads, Body 2.9x1.3mm, Pitch 0.95mm, Lead Span 2.5mm, IPC Medium Density"
  rrect50% 1x0.6 smd: 1(-1.2,0.95) 2(-1.2,-0.95) 3(1.2,0)
  silkscreen extent -1.63,-1.5 0.7,1.5, body extent -1.16,-1.45 1.21,1.45, height 1
STANDOFF_FAB_0022 [mm] "STANDOFF, 2 POS, THRU"
  round 3.18 hole 3.18 unplated: ""(-6.35,0) ""(6.35,0)
  Keep-Out Layer circle w0.05: c-6.35,0 r2.352
  Keep-Out Layer circle w0.05: c6.35,0 r2.352
  silkscreen extent -11.43,-6.35 11.43,6.35, body extent -11.43,-6.35 11.43,6.35, height 24.13
SW_218-12LPST [mm] "SMD, 24-Leads, Body 16.41x5.8mm, Pitch 1.27mm"
  rrect13% 1.27x0.76 smd: 1(-3.81,6.985) 2(-3.81,5.715) 3(-3.81,4.445) 4(-3.81,3.175) 5(-3.81,1.905) 6(-3.81,0.635) 7(-3.81,-0.635) 8(-3.81,-1.905) 9(-3.81,-3.175) 10(-3.81,-4.445) 11(-3.81,-5.715) 12(-3.81,-6.985) 13(3.81,-6.985) 14(3.81,-5.715) 15(3.81,-4.445) 16(3.81,-3.175) 17(3.81,-1.905) 18(3.81,-0.635) 19(3.81,0.635) 20(3.81,1.905) 21(3.81,3.175) 22(3.81,4.445) 23(3.81,5.715) 24(3.81,6.985)
  body extent -4.22,-8.2 4.22,8.2, height 2.63
SW_KMR243GLFG [mm] "SMD, 5-Leads, Body 4.2x2.8mm"
  rrect11% 0.9x1 smd: 1(-2.05,0.8) 2(2.05,0.8) 3(-2.05,-0.8) 4(2.05,-0.8)
  rrect18% 1.7x0.55 smd: 5(0,1.425)
  silkscreen extent -2.2,1.85 -1.79,2.26, body extent -2.3,-1.4 2.3,1.4, height 1.92
TI_Stacked_Overlay_Small [mil]
  silkscreen extent -418,-98 418,98
TLMx1000_Red [mm] "SMD, 2-Leads, Body 1.6x0.8mm"
  rrect17% 0.6x0.8 smd: 1(-0.725,0) 2(0.725,0)
  silkscreen extent -0.97,-0.8 1.6,0.8, body extent -0.85,-0.45 0.85,0.45, height 0.65
TLMx1000_Yellow [mm] "SMD, 2-Leads, Body 1.6x0.8mm"
  rrect17% 0.6x0.8 smd: 1(-0.725,0) 2(0.725,0)
  silkscreen extent -0.97,-0.8 1.6,0.8, body extent -0.85,-0.45 0.85,0.45, height 0.65
TSSOP-8 [mm] "TSSOP, 8-Leads, Body 3.1x4.5mm (max), Pitch 0.65mm, IPC Medium Density"
  rrect50% 1.7x0.35 smd: 1(-2.85,0.975) 2(-2.85,0.325) 3(-2.85,-0.325) 4(-2.85,-0.975) 5(2.85,-0.975) 6(2.85,-0.325) 7(2.85,0.325) 8(2.85,0.975)
  silkscreen extent -4.23,-1.55 1.6,1.55, body extent -3.2,-1.55 3.2,1.55, height 1.07
TSW-102-07-X-S [mm] "Samtec 100 mil 1x2 head, 230 mil above insulator"
  rrect6% 1.65x1.65 hole 1.016: 1(-1.27,0)
  round 1.65 hole 1.016: 2(1.27,0)
  silkscreen extent -3.42,-1.4 2.72,1.4, body extent -2.54,-1.27 2.54,1.27, height 8.38
TSW-105-07-G-D [mm] "Samtec 100mil, 2x5, 230 mil above insulator"
  rrect6% 1.65x1.65 hole 1.016: 1(-5.08,-1.27)
  round 1.65 hole 1.016: 2(-5.08,1.27) 3(-2.54,-1.27) 4(-2.54,1.27) 5(0,-1.27) 6(0,1.27) 7(2.54,-1.27) 8(2.54,1.27) 9(5.08,-1.27) 10(5.08,1.27)
  silkscreen extent -8,-2.54 6.35,2.54, body extent -6.35,-2.54 6.35,2.54, height 8.38
TSW-108-07-G-D [mm] "Samtec 100mil, 2x8, 230 mil above insulator"
  rrect6% 1.65x1.65 hole 1.016: 1(-8.89,-1.27)
  round 1.65 hole 1.016: 2(-8.89,1.27) 3(-6.35,-1.27) 4(-6.35,1.27) 5(-3.81,-1.27) 6(-3.81,1.27) 7(-1.27,-1.27) 8(-1.27,1.27) 9(1.27,-1.27) 10(1.27,1.27) 11(3.81,-1.27) 12(3.81,1.27) 13(6.35,-1.27) 14(6.35,1.27) 15(8.89,-1.27) 16(8.89,1.27)
  silkscreen extent -10.16,-4.24 10.16,2.54, body extent -10.16,-2.54 10.16,2.54, height 8.38
WEEE_Minimum [mil] "WEEElie bin"
  silkscreen extent -95,-172 99,104
XAL5030 [mil] "Coilcraft XAL5030 12/12/11"
  rect 46x183 smd: 1(-65,0) 2(65,0)
  silkscreen extent -108,-112 108,112, body extent -108,-112 108,112, height 122

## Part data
C1 C2 C4 C27 C32 C33 C34 C36 C40 C43 C44 C45 C49 C50 C52 C54 C55 C56 C57 C59 C63 C67 C68 C70 C72 C73 C92 C93 C94 C95 C114 C115 C116 C117: library part CMP-0078241-1, "CAP, CERM, 0.1 µF, 10 V,+/- 10%, X7R, 0402", Cap_Case=0402, Manufacturer=Kemet, Supplier Part Number 1=399-3520-1-ND, TempCo=X7R, Tolerance_%=10%, Value2=10V, ValueDisplayed=0.1µF
C3 C5: library part CMP-0078221-1, "CAP, CERM, 4700 pF, 50 V,+/- 10%, X7R, 0402", Cap_Case=0402, Manufacturer=TDK, Supplier Part Number 1=445-1258-1-ND, TempCo=X7R, Tolerance_%=10%, Value2=50V, ValueDisplayed=4700pF
C6 C7 C8 C25 C26 C71 C74 C77: library part CMP-0006325-2, "CAP, CERM, 0.1 uF, 50 V, +/- 10%, X7R, AEC-Q200 Grade 1, 0402", Cap_Case=0402, Manufacturer=TDK, Supplier Part Number 1=445-6899-1-ND, TempCo=X7R, Tolerance_%=10%, Value1="0.039064 ohm", Value2=50V, ValueDisplayed=0.1uF
C9 C10 C11 C12: library part CMP-0008017-2, "CAP, CERM, 10 uF, 10 V, +/- 10%, X7R, 0805", Cap_Case=0805, Manufacturer=MuRata, Supplier Part Number 1=490-10674-1-ND, TempCo=X7R, Tolerance_%=10%, Value1=Unknown, Value2=10V, ValueDisplayed=10uF
C13 C14 C15 C16: library part CMP-0008811-2, "CAP, CERM, 22 uF, 10 V, +/- 10%, X7R, AEC-Q200 Grade 1, 1206", Cap_Case=1206, Manufacturer=MuRata, TempCo=X7R, Tolerance_%=10%, Value1=Unknown, Value2=10V, ValueDisplayed=22uF
C17: library part CMP-0078265-1, "CAP, CERM, 0.22 µF, 16 V,+/- 10%, X7R, AEC-Q200 Grade 1, 0402", Cap_Case=0402, Manufacturer=MuRata, Supplier Part Number 1=490-10671-1-ND, TempCo=X7R, Tolerance_%=10%, Value2=16V, ValueDisplayed=0.22µF
C18 C19 C20 C21: library part CMP-0078223-1, "CAP, CERM, 390 pF, 50 V,+/- 5%, C0G/NP0, AEC-Q200 Grade 0, 0402", Cap_Case=0402, Manufacturer=TDK, Supplier Part Number 1=445-12137-1-ND, TempCo=C0G/NP0, Tolerance_%=5%, Value2=50V, ValueDisplayed=390pF
C22 C23: library part CMP-0082253-1, "CAP, TA, 47 µF, 50 V, +/- 10%, 0.24 ohm, SMD", Cap_Case=7.6x6x6.4mm, Manufacturer=Vishay-Sprague, Supplier Part Number 1=718-1408-1-ND, Tolerance_%=10%, Value1="0.24 ohm", Value2=50V, ValueDisplayed=47µF
C24: library part CMP-0006351-2, "CAP, CERM, 0.1 uF, 16 V, +/- 10%, X7R, 0402", Cap_Case=0402, Manufacturer=MuRata, Supplier Part Number 1=490-4759-2-ND, TempCo=X7R, Tolerance_%=10%, Value1=Unknown, Value2=16V, ValueDisplayed=0.1uF
C28: library part CMP-0007111-4, "CAP, CERM, 1 uF, 6.3 V, +/- 10%, X7R, 0603", Cap_Case=0603, Manufacturer="Samsung Electro-Mechanics", TempCo=X7R, Tolerance_%=10%, Value1=Unknown, Value2=6.3V, ValueDisplayed=1uF
C29: library part CMP-0007359-4, "CAP, CERM, 0.1 uF, 6.3 V, +/- 10%, X7R, 0603", Cap_Case=0603, Manufacturer=MuRata, Supplier Part Number 1=GRM188R70J104KA01D-ND, TempCo=X7R, Tolerance_%=10%, Value1=Unknown, Value2=6.3V, ValueDisplayed=0.1uF
C30 C110 C113: library part CMP-0006332-2, "CAP, CERM, 1000 pF, 100 V, +/- 10%, X7S, AEC-Q200 Grade 1, 0402", Cap_Case=0402, Manufacturer=TDK, Supplier Part Number 1=445-6904-1-ND, TempCo=X7S, Tolerance_%=10%, Value1="2.71151 ohm", Value2=100V, ValueDisplayed=1000pF
C31 C66 C69 C111: library part CMP-0007136-5, "CAP, CERM, 1 uF, 16 V, +/- 10%, X7R, AEC-Q200 Grade 1, 0603", Cap_Case=0603, Manufacturer=MuRata, Supplier Part Number 1=490-5241-6-ND, TempCo=X7R, Tolerance_%=10%, Value1=Unknown, Value2=16V, ValueDisplayed=1uF
C35 C37 C41 C120: library part CMP-0078222-1, "CAP, CERM, 1 µF, 6.3 V,+/- 20%, X7S, 0402", Cap_Case=0402, Manufacturer=TDK, Supplier Part Number 1=445-9080-1-ND, TempCo=X7S, Tolerance_%=20%, Value2=6.3V, ValueDisplayed=1µF
C38: library part CMP-0078220-1, "CAP, CERM, 0.01 µF, 25 V,+/- 10%, X7R, 0402", Cap_Case=0402, Manufacturer=TDK, Supplier Part Number 1=445-1260-1-ND, TempCo=X7R, Tolerance_%=10%, Value2=25V, ValueDisplayed=0.01µF
C39 C62 C65 C88: library part CMP-0006302-2, "CAP, CERM, 2.2 uF, 10 V, +/- 10%, X7S, 0402", Cap_Case=0402_065, Manufacturer=TDK, Supplier Part Number 1=445-9097-1-ND, TempCo=X7S, Tolerance_%=10%, Value1="0.005925 ohm", Value2=10V, ValueDisplayed=2.2uF
C42 C46: library part CMP-0078218-1, "CAP, CERM, 0.01 µF, 16 V,+/- 10%, X7R, 0402", Cap_Case=0402, Manufacturer=Kemet, Supplier Part Number 1=399-1038-1-ND, TempCo=X7R, Tolerance_%=10%, Value2=16V, ValueDisplayed=0.01µF
C47 C48 C60 C61: library part CMP-0006494-2, "CAP, CERM, 8 pF, 50 V, +/- 6%, C0G/NP0, 0402", Cap_Case=0402, Manufacturer=MuRata, Supplier Part Number 1=490-5867-1-ND, TempCo=C0G/NP0, Tolerance_%=6%, Value1=Unknown, Value2=50V, ValueDisplayed=8pF
C51 C53 C58: library part CMP-0007058-4, "CAP, CERM, 4.7 uF, 10 V, +/- 10%, X7S, 0603", Cap_Case=0603, Manufacturer=TDK, Supplier Part Number 1=445-14258-1-ND, TempCo=X7S, Tolerance_%=10%, Value1=Unknown, Value2=10V, ValueDisplayed=4.7uF
C64: library part CMP-0078217-1, "CAP, CERM, 15 pF, 50 V,+/- 1%, C0G/NP0, 0402", Cap_Case=0402, Manufacturer=AVX, Supplier Part Number 1=478-5126-1-ND, TempCo=C0G/NP0, Tolerance_%=1%, Value2=50V, ValueDisplayed=15pF
C75 C76: library part CMP-0006906-5, "CAP, CERM, 2.2 uF, 10 V, +/- 10%, X5R, 0603", Cap_Case=0603, Manufacturer=Kemet, Supplier Part Number 1=399-4911-1-ND, TempCo=X5R, Tolerance_%=10%, Value1=Unknown, Value2=10V, ValueDisplayed=2.2uF
C78 C96: library part CMP-0006717-2, "CAP, CERM, 0.47 uF, 6.3 V, +/- 10%, X7R, 0402", Cap_Case=0402, Manufacturer="Taiyo Yuden", Supplier Part Number 1=587-3765-1-ND, TempCo=X7R, Tolerance_%=10%, Value1=Unknown, Value2=6.3V, ValueDisplayed=0.47uF
C79 C97: library part CMP-0011176-2, "CAP, AL, 10 uF, 50 V, +/- 20%, 1.52 ohm, AEC-Q200 Grade 2, SMD", Cap_Case=C, Manufacturer=Panasonic, Supplier Part Number 1=PCE3808CT-ND, Tolerance_%=20%, Value1="1.52 ohm", Value2=50V, ValueDisplayed=10uF
C80 C83 C98 C101: library part CMP-0009227-2, "CAP, CERM, 10 uF, 50 V, +/- 20%, X7R, 1210", Cap_Case=1210, Manufacturer=MuRata, Supplier Part Number 1=490-12775-1-ND, TempCo=X7R, Tolerance_%=20%, Value1=Unknown, Value2=50V, ValueDisplayed=10uF
C81 C84 C99 C102: library part CMP-0009075-1, "CAP, CERM, 0.1 uF, 50 V, +/- 10%, X7R, 1210", Cap_Case=1210, Manufacturer=Kemet, Supplier Part Number 1=399-1267-1-ND, TempCo=X7R, Tolerance_%=10%, Value1=Unknown, Value2=50V, ValueDisplayed=0.1uF
C82 C85 C100 C103: library part CMP-0007718-2, "CAP, CERM, 0.01 uF, 50 V, +/- 10%, X7R, 0805", Cap_Case=0805, Manufacturer=Kemet, Supplier Part Number 1=399-1158-1-ND, TempCo=X7R, Tolerance_%=10%, Value1="1.739 ohm", Value2=50V, ValueDisplayed=0.01uF
C86 C104: library part CMP-0006201-2, "CAP, CERM, 0.1 uF, 16 V, +/- 10%, X7R, 0402", Cap_Case=0402, Manufacturer=AVX, Supplier Part Number 1=478-7888-1-ND, TempCo=X7R, Tolerance_%=10%, Value1=Unknown, Value2=16V, ValueDisplayed=0.1uF
C87 C108: library part CMP-0007870-2, "CAP, CERM, 4.7 uF, 25 V, +/- 10%, X7R, 0805", Cap_Case=0805, Manufacturer=TDK, Supplier Part Number 1=445-5972-1-ND, TempCo=X7R, Tolerance_%=10%, Value1=Unknown, Value2=25V, ValueDisplayed=4.7uF
C89 C90 C91 C105 C106 C107: library part CMP-0081783-1, "CAP, CERM, 22 µF, 16 V,+/- 10%, X7R, 1210", Cap_Case=1210, Manufacturer=Samsung, Supplier Part Number 1=1276-3394-1-ND, TempCo=X7R, Tolerance_%=10%, Value2=16V, ValueDisplayed=22µF
C109 C112: library part CMP-0006856-6, "CAP, CERM, 0.1 uF, 25 V, +/- 5%, X7R, 0603", Cap_Case=0603, Manufacturer=Kemet, Supplier Part Number 1=399-1282-1-ND, TempCo=X7R, Tolerance_%=5%, Value1=Unknown, Value2=25V, ValueDisplayed=0.1uF
C119: library part CMP-0006242-2, "CAP, CERM, 33 pF, 50 V, +/- 5%, C0G/NP0, 0402", Cap_Case=0402, Manufacturer=Kemet, Supplier Part Number 1=399-1017-1-ND, TempCo=C0G/NP0, Tolerance_%=5%, Value1=Unknown, Value2=50V, ValueDisplayed=33pF
"CAUTION HOT SURFACE1": library part CMP-0074837-1, "IEC 61010-1 Hot Surface Warning"
D1: library part CMP-0005561-2, "Diode, TVS, Uni, 30 V, 48.4 Vc, SMB", Manufacturer="Diodes Inc.", Power_W=5W, Supplier Part Number 1=SMBJ30A-FDICT-ND
D4 D5 D6 D7 DS1 DS2: library part CMP-0078196-1, "LED, Yellow, SMD", Color=yellow, Manufacturer=Vishay-Semiconductor, Power_TotalModule=40mW, Supplier Part Number 1=TLMY1000-GS08CT-ND, Value1=.04W, Value2=1.8V
D8 D9 D10 DS3 DS4: library part CMP-0078197-1, "LED, Red, SMD", Color=Red, Manufacturer=Vishay-Semiconductor, Power_TotalModule=40mW, Supplier Part Number 1=TLMS1000-GS08CT-ND, Value1=.04W, Value2=1.8V
D11 D14: library part CMP-0002873-1, "LED, Green, SMD", Color=green, Manufacturer=Rohm, Supplier Part Number 1=511-1592-1-ND, Value1=W, Value2=2.2V
F1: library part CMP-0003458-1, "Fuse, 5 A, 32VAC/VDC, SMD", Irating_A=5A, Manufacturer=Littelfuse, Supplier Part Number 1=F1608CT-ND
FB1 FB2: library part CMP-0003364-1, "Ferrite Bead, 30 ohm @ 100 MHz, 4 A, 0805", Manufacturer=MuRata, Supplier Part Number 1=490-11049-1-ND, Value1="0.014 ohm", Value2=4A, ValueDisplayed="30 ohm"
FID1 FID2 FID3 FID4 FID5 FID6: library part CMP-0077181-1, "Fiducial mark.  There is nothing to buy or mount.", Manufacturer=N/A
J1 J2: library part CMP-0075352-1, "Terminal Block, 3.5mm, 3x1, Tin, R/A, TH", Color=Blue, Current_A=10A, Manufacturer="On-Shore Technology", Supplier Part Number 1=ED2636-ND, Voltage_V=125V
J3: library part CMP-0055788-1, "UMC Straight Jack Receptacle, 50 Ohm, Gold, SMT", Manufacturer="Cinch Connectivity", Supplier Part Number 1=J983CT-ND
J4 J17: library part CMP-0075558-2, "Header(Shrouded), 19.7mil, 30x2, Gold, SMT", Manufacturer=Samtec, Supplier Part Number 1=SAM8185-ND
J5 J6: library part CMP-0078182-1, "Receptacle, 2.54mm, 10x2, Gold with Tin tail, SMT", Color=Black, Current_A=5.2A, Manufacturer=Samtec, Supplier Part Number 1=SAM1150-10-ND, Voltage_V=405V
J7 J8: library part CMP-0078183-1, "Receptacle, 2.54mm, 3x1, Gold with Tin tail, SMT", Color=Black, Current_A=5.2A, Manufacturer=Samtec, Supplier Part Number 1=SAM1152-03-ND, Voltage_V=405V
J9 J10: library part CMP-0075524-1, "Receptacle, 0.5 mm, 30x2, Gold, TH", Color=Black, Manufacturer=Samtec, Supplier Part Number 1=SAM8180-ND
J11 J12: library part CMP-0055293-1, "Connector, Receptacle, Micro-USB Type B, R/A, Bottom Mount SMT", Manufacturer=Molex, Supplier Part Number 1=WM1399CT-ND
J13 J14 J15 J27 J28: library part CMP-0055332-1, "Header, 2.54mm, 3x1, Tin, TH", Color=Black, Current_A=4A, Manufacturer=Molex, Supplier Part Number 1=WM50016-03-ND, Voltage_V=250V
J16: library part CMP-0075410-2, "Header, 100mil, 5x2, Gold, TH", Color=Black, Current_A=6.3A, Manufacturer=Samtec, Supplier Part Number 1=SAM1028-05-ND, Voltage_V=550V
J18 J20: library part CMP-0075418-1, "Header, 100mil, 8x2, Gold, TH", Color=Black, Current_A=6.3A, Manufacturer=Samtec, Supplier Part Number 1=SAM1028-08-ND, Voltage_V=550V
J19: library part CMP-0081507-3, "Header, 2.54mm, 13Pos, Gold with Tin tail, TH", Color=Black, Manufacturer=Samtec, Supplier Part Number 1=TSW-107-07-L-D-006-ND
L1 L2 L3 L4: library part CMP-0058946-1, "Inductor, Shielded, 470 nH, 4.7 A, 0.021 ohm, SMD", Manufacturer="MuRata Toko", PartNumber=DFE252012P-R47M{}P2, Value1="0.021 ohm", Value2=4.7A, ValueDisplayed=470nH
L5 L6: library part CMP-0081523-1, "Ferrite Bead, 600 ohm @ 100 MHz, 0.3 A, 0402", Manufacturer=MuRata, Supplier Part Number 1=490-3998-1-ND, Value1="0.7 ohm", Value2=0.3A, ValueDisplayed="600 ohm"
L7: library part CMP-0058739-1, "Inductor, Multilayer, Ferrite, 1 uH, 0.8 A, 0.19 ohm, SMD", Manufacturer=MuRata, Supplier Part Number 1=490-4992-1-ND, Value1="0.19 ohm", Value2=0.8A, ValueDisplayed=1uH
L8 L9: library part CMP-0061001-1, "Inductor, Shielded, Composite, 2.2 uH, 9.2 A, 0.01 ohm, SMD", Manufacturer=Coilcraft, Value1="0.01 ohm", Value2=9.2A, ValueDisplayed=2.2uH
LBL1: library part CMP-0003625-1, "Thermal Transfer Printable Labels, 0.650\" W x 0.200\" H - 10,000 per roll", Manufacturer=Brady, Supplier Part Number 1=97C5133
Logo1: library part CMP-0074838-1, "Texas Instrument Corporate Signature"
Logo2: library part CMP-0074844-1
Logo3: library part CMP-0074847-1, "FCC_disclaimer"
Logo4: library part CMP-0074769-1
P1 P3 P4 P5 P6 P7: library part CMP-0075405-1, "Header, 100mil, 2x1, Gold, TH", Color=Black, Current_A=6.3A, Manufacturer=Samtec, Supplier Part Number 1=SAM1029-02-ND, Voltage_V=550V
P2: library part CMP-0078270-1, "DC POWER JACK, R/A, TH", Color=Black, Current_A=5A, Manufacturer="CUI Inc.", Supplier Part Number 1=CP-002AH-ND, Voltage_V=24V
Q1 Q2: library part CMP-0000947-2, "MOSFET, N-CH, 100 V, 0.17 A, SOT-23", Alternate Manufacturer=None, Manufacturer="Fairchild Semiconductor", Supplier Part Number 1=BSS123NCT-ND, Value1=1, Value2="1.8 nC"
R1 R6 R8 R15 R20 R21 R27 R28 R29 R30 R32 R33 R35 R36 R38 R39 R40 R42 R43 R44 R45 R46 R47 R48 R52 R53 R54 R75 R96 R131 R144 R145 R146 R157 R160 R181 R184 R192 R194 R195 R196 R198 R199 R200 R202 R205 R207 R210 R211 R215 R216 R217 R224 R227 R229 R230 R231 R233 R234 R236 R237 R238 R239 R240 R246 R268 R269 R270 R273 R276 R281 R283 R290 R294 R295 R296 R297 R298 R346 R347 R348 R349 R350 R351 R353 R354 R356 R357 R358 R359 R360 R361 R362 R398: library part CMP-0026992-3, "RES, 0, 5%, 0.1 W, AEC-Q200 Grade 0, 0402", Manufacturer=Panasonic, Power_W=100mW, Supplier Part Number 1=P0.0JCT-ND, TempCo="600 ppm/C", Tolerance_%=5%, Value2=0.1W, Value_Code=0000, ValueDisplayed=0
R2 R7: library part CMP-0026491-1, "RES, 61.9, 1%, 0.063 W, 0402", Manufacturer=Vishay-Dale, Power_W=63mW, Supplier Part Number 1=541-61.9LCT-ND, TempCo="100 ppm/C", Tolerance_%=1%, Value2=0.063W, Value_Code=61R9, ValueDisplayed=61.9
R3 R12 R74 R80 R106 R150 R158 R179 R180: library part CMP-0026992-2, "RES, 0, 5%, 0.063 W, 0402", Manufacturer=Panasonic, Power_W=63mW, Supplier Part Number 1=P0.0JCT-ND, TempCo="600 ppm/C", Tolerance_%=5%, Value2=0.063W, Value_Code=0000, ValueDisplayed=0
R4 R5 R18 R19 R23 R24 R25 R26 R37 R51 R57 R58 R60 R61 R71 R95 R109 R110 R120 R126 R133 R137 R141 R151 R168 R176 R177 R203 R209 R250 R260 R299 R301 R307 R308 R310 R311 R314 R316 R317 R325 R327 R328 R330 R331 R332 R395 R399 R400 R401 R402: library part CMP-0025958-2, "RES, 10.0 k, 1%, 0.063 W, 0402", Manufacturer=Vishay-Dale, Power_W=63mW, Supplier Part Number 1=541-10.0KLCT-ND, TempCo="100 ppm/C", Tolerance_%=1%, Value2=0.063W, Value_Code=10k0, ValueDisplayed=10.0k
R9 R13 R22 R69 R185 R186 R187 R189 R190 R201 R274 R275 R364 R369: library part CMP-0025958-3, "RES, 10.0 k, 1%, 0.063 W, AEC-Q200 Grade 0, 0402", Manufacturer=Vishay-Dale, Power_W=63mW, Supplier Part Number 1=541-10.0KLCT-ND, TempCo="100 ppm/C", Tolerance_%=1%, Value2=0.063W, Value_Code=10k0, ValueDisplayed=10.0k
R10 R114 R117 R118 R125 R128 R191 R251 R252 R253: library part CMP-0078212-1, "RES, 510, 5%, 0.1 W, AEC-Q200 Grade 0, 0402", Manufacturer=Panasonic, Power_W=100mW, Supplier Part Number 1=P510JCT-ND, TempCo="200 ppm/C", Tolerance_%=5%, Value2=0.1W, Value_Code=510R, ValueDisplayed=510
R11 R31: library part CMP-0026491-2, "RES, 61.9, 1%, 0.063 W, AEC-Q200 Grade 0, 0402", Manufacturer=Vishay-Dale, Power_W=63mW, Supplier Part Number 1=541-61.9LCT-ND, TempCo="100 ppm/C", Tolerance_%=1%, Value2=0.063W, Value_Code=61R9, ValueDisplayed=61.9
R14 R67 R70 R72 R76 R77 R78 R79 R81 R82 R85 R86 R88 R89 R90 R91 R92 R93 R94 R99 R100 R121 R161 R162 R171 R172 R173 R174 R175 R178 R393 R394: library part CMP-0027008-3, "RES, 0, 5%, 0.05 W, 0201", Manufacturer=Vishay-Dale, Power_W=50mW, Supplier Part Number 1=72M6743, TempCo=ppm/C, Tolerance_%=5%, Value2=0.05W, Value_Code=0000, ValueDisplayed=0
R16 R17 R41 R62 R63 R65 R66 R68 R241 R243 R244 R261 R262 R338 R339: library part CMP-0026938-5, "RES, 4.7 k, 5%, 0.063 W, AEC-Q200 Grade 0, 0402", Manufacturer=Vishay-Dale, Power_W=63mW, Supplier Part Number 1=541-4.7KJCT-ND, TempCo="200 ppm/C", Tolerance_%=5%, Value2=0.063W, Value_Code=4k70, ValueDisplayed=4.7k
R34 R119 R124 R127 R129 R159 R242 R245 R329 R367 R368 R370: library part CMP-0026993-2, "RES, 100, 5%, 0.1 W, AEC-Q200 Grade 0, 0402", Manufacturer=Panasonic, Power_W=100mW, Supplier Part Number 1=P100JCT-ND, TempCo="200 ppm/C", Tolerance_%=5%, Value2=0.1W, Value_Code=100R, ValueDisplayed=100
R49 R50 R122 R232 R235 R286 R287 R288 R289 R291: library part CMP-0081623-1, "RES, 0.002, 1%, 1 W, AEC-Q200 Grade 0, 1206", Manufacturer=Rohm, Power_W=1W, Supplier Part Number 1=RHM.002ALCT-ND, TempCo="100 ppm/C", Tolerance_%=1%, Value_Code=2L000, ValueDisplayed=0.002
R55 R56 R64 R73 R111 R130 R247 R248 R249: library part CMP-0025950-2, "RES, 100 k, 1%, 0.063 W, 0402", Manufacturer=Vishay-Dale, Power_W=63mW, Supplier Part Number 1=541-100KLCT-ND, TempCo="100 ppm/C", Tolerance_%=1%, Value2=0.063W, Value_Code=100k
R59 R113 R115 R116: library part CMP-0016044-2, "RES, 0, 5%, 0.75 W, AEC-Q200 Grade 0, 2010", Manufacturer=Vishay-Dale, Power_W=750mW, Supplier Part Number 1=541-0.0WCT-ND, TempCo=ppm/C, Tolerance_%=5%, Value2=0.75W, Value_Code=0000, ValueDisplayed=0
R97 R98: library part CMP-0026414-1, "RES, 4.99 k, 1%, 0.063 W, 0402", Manufacturer=Vishay-Dale, Power_W=63mW, Supplier Part Number 1=541-4.99KLCT-ND, TempCo="100 ppm/C", Tolerance_%=1%, Value2=0.063W, Value_Code=4k99, ValueDisplayed=4.99k
R101 R102 R103 R104: library part CMP-0026363-1, "RES, 3.83, 1%, 0.063 W, 0402", Manufacturer=Vishay-Dale, Power_W=63mW, Supplier Part Number 1=541-3.83LLCT-ND, TempCo="100 ppm/C", Tolerance_%=1%, Value2=0.063W, Value_Code=3R83, ValueDisplayed=3.83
